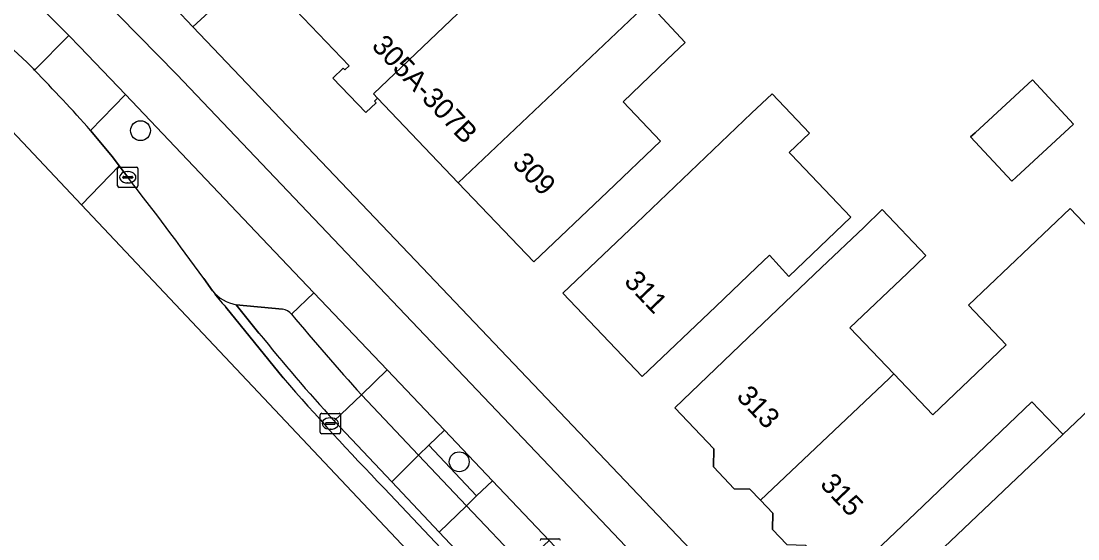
# Model space of a CAD drawing. Extents: x 162523 to 163266, y 381230 to 382050.
# Drawn here: x 162884.1 to 162936.1, y 381486.7 to 381512.1 of the extents above; entities that cross this region are included whole.
import ezdxf

# ---------------------------------------------------------------- set-up
doc = ezdxf.new("R2010")
doc.units = 0
for name, color, linetype in [('IMGEO_Berm_groen', 7, 'Continuous'), ('IMGEO_Berm_open', 7, 'Continuous'), ('IMGEO_Boom', 7, 'Continuous'), ('IMGEO_Erf', 7, 'Continuous'), ('IMGEO_Fietspad_gesloten', 7, 'Continuous'), ('IMGEO_Kolk', 7, 'Continuous'), ('IMGEO_Pand', 7, 'Continuous'), ('IMGEO_Pand_nummerreeks', 7, 'Continuous'), ('IMGEO_Parkeervlak_open', 7, 'Continuous'), ('IMGEO_Rijbaan_lokaal_gesloten', 7, 'Continuous'), ('IMGEO_Rijbaan_lokaal_open', 7, 'Continuous'), ('IMGEO_Voetpad_open', 7, 'Continuous')]:
    doc.layers.add(name, color=color, linetype=linetype)

msp = doc.modelspace()

# ---------------------------------------------------------------- linework, layer by layer
at = {"layer": 'IMGEO_Berm_groen'}
for points in [[(162895.973, 381501.441), (162889.27, 381508.508), (162887.563, 381506.746), (162888.633, 381505.447), (162888.972, 381504.997), (162889.389, 381504.443)], [(162897.444, 381497.706), (162898.543, 381498.758), (162895.973, 381501.441)], [(162893.123, 381499.458), (162893.553, 381498.859)], [(162894.726, 381498.173), (162896.997, 381497.958)]]:
    msp.add_lwpolyline(points, dxfattribs=at)
msp.add_lwpolyline([(162904.958, 381492.006), (162904.184, 381491.264), (162906.542, 381488.775), (162907.318, 381489.521)], close=True, dxfattribs=at)
for centre, radius, start, end in [((162751.131, 381396.99), 175.104, 35.81589, 37.85399), ((162895.072, 381500.111), 1.968, 219.4851, 259.8746), ((162896.897, 381497.258), 0.707, 39.2967, 81.8783)]:
    msp.add_arc(centre, radius, start, end, dxfattribs=at)
at = {"layer": 'IMGEO_Berm_open'}
msp.add_lwpolyline([(162904.184, 381491.264), (162903.687, 381490.773), (162906.04, 381488.29), (162906.542, 381488.775)], close=True, dxfattribs=at)
at = {"layer": 'IMGEO_Boom'}
for centre in [(162890.014, 381506.734), (162905.684, 381490.454)]:
    msp.add_circle(centre, 0.489, dxfattribs=at)
at = {"layer": 'IMGEO_Erf'}
for points in [[(162895.705, 381514.707), (162892.594, 381511.832), (162903.859, 381500), (162947.952, 381453.669)], [(162915.003, 381512.983), (162916.796, 381511.073), (162915.915, 381510.232), (162913.74, 381508.157), (162915.584, 381506.224), (162912.972, 381503.732), (162909.354, 381500.28), (162905.639, 381504.174), (162901.67, 381508.333), (162901.52, 381508.19), (162901.603, 381508.103), (162901.097, 381507.619), (162899.47, 381509.321), (162899.976, 381509.805), (162900.058, 381509.718), (162900.275, 381509.926), (162895.749, 381514.66)], [(162921.802, 381486.381), (162921.086, 381487.132), (162921.104, 381487.935), (162920.503, 381488.564), (162919.981, 381489.111), (162919.209, 381489.129), (162918.187, 381490.2), (162918.208, 381491.09), (162916.28, 381493.109), (162919.897, 381496.562), (162923.5, 381500), (162925.574, 381501.979), (162926.488, 381502.852), (162928.636, 381500.6), (162927.722, 381499.728), (162924.9, 381497.035), (162927.06, 381494.771), (162928.973, 381492.767), (162931.838, 381495.502), (162932.581, 381496.211), (162930.729, 381498.15), (162935.735, 381502.902), (162938.652, 381499.847)], [(162925.959, 381482.861), (162935.374, 381491.799), (162935.349, 381491.825), (162933.844, 381493.401), (162928.117, 381487.935), (162924.5, 381484.482)]]:
    msp.add_lwpolyline(points, dxfattribs=at)
for points in [[(162933.871, 381509.239), (162935.892, 381507.051), (162933.071, 381504.445), (162932.855, 381504.246), (162930.834, 381506.434), (162931.05, 381506.633)], [(162923.972, 381503.5), (162924.946, 381502.479), (162921.897, 381499.569), (162920.938, 381500.605), (162920.304, 381500), (162918.305, 381498.093), (162914.687, 381494.641), (162910.779, 381498.736), (162912.104, 381500), (162914.397, 381502.188), (162920.065, 381507.596), (162921.066, 381508.551), (162922.916, 381506.613), (162921.914, 381505.657), (162922.01, 381505.557)]]:
    msp.add_lwpolyline(points, close=True, dxfattribs=at)
at = {"layer": 'IMGEO_Fietspad_gesloten'}
for points in [[(162884.173, 381513.735), (162886.411, 381511.49), (162886.484, 381511.417), (162887.036, 381510.863), (162889.27, 381508.508), (162895.973, 381501.441), (162898.543, 381498.758), (162902.145, 381494.967), (162904.958, 381492.006), (162907.318, 381489.521), (162910.115, 381486.578), (162917.623, 381478.675), (162920.321, 381475.835), (162923.037, 381472.961), (162924.045, 381471.906), (162924.447, 381471.486), (162928.036, 381467.73), (162928.672, 381467.066), (162936.08, 381459.315), (162938.891, 381456.375)], [(162961.518, 381436.339), (162959.423, 381438.485), (162924.904, 381474.653), (162912.667, 381487.562), (162891.8, 381509.488), (162888.028, 381513.353)]]:
    msp.add_lwpolyline(points, dxfattribs=at)
at = {"layer": 'IMGEO_Kolk'}
for p, q in [((162888.963, 381504.943), (162889.815, 381504.943)), ((162888.888, 381504.017), (162888.888, 381504.869)), ((162889.147, 381504.437), (162889.147, 381504.449)), ((162889.19, 381504.486), (162889.588, 381504.486)), ((162889.376, 381504.723), (162889.401, 381504.723)), ((162889.631, 381504.449), (162889.631, 381504.437)), ((162889.889, 381504.869), (162889.889, 381504.017)), ((162889.815, 381503.943), (162888.963, 381503.943)), ((162889.585, 381504.4), (162889.187, 381504.4)), ((162889.399, 381504.163), (162889.374, 381504.163)), ((162898.849, 381491.909), (162898.849, 381492.761)), ((162898.924, 381492.835), (162899.776, 381492.835)), ((162899.337, 381492.615), (162899.362, 381492.615)), ((162899.85, 381492.761), (162899.85, 381491.909)), ((162899.108, 381492.329), (162899.108, 381492.341)), ((162899.546, 381492.292), (162899.148, 381492.292)), ((162899.151, 381492.378), (162899.549, 381492.378)), ((162899.36, 381492.055), (162899.335, 381492.055)), ((162899.592, 381492.341), (162899.592, 381492.329)), ((162899.776, 381491.835), (162898.924, 381491.835)), ((162909.733, 381486.663), (162910.585, 381486.663))]:
    msp.add_line(p, q, dxfattribs=at)
for points in [[(162888.963, 381504.943), (162889.815, 381504.943)], [(162888.888, 381504.017), (162888.888, 381504.869)], [(162889.889, 381504.869), (162889.889, 381504.017)], [(162889.815, 381503.943), (162888.963, 381503.943)], [(162898.849, 381491.909), (162898.849, 381492.761)], [(162898.924, 381492.835), (162899.776, 381492.835)], [(162899.85, 381492.761), (162899.85, 381491.909)], [(162899.776, 381491.835), (162898.924, 381491.835)], [(162909.733, 381486.663), (162910.585, 381486.663)]]:
    msp.add_lwpolyline(points, dxfattribs=at)
for centre, radius, start, end in [((162888.965, 381504.867), 0.0765, 91.552, 178.448), ((162888.965, 381504.867), 0.0765, 91.552, 178.448), ((162889.813, 381504.867), 0.0765, 1.552, 88.448), ((162889.813, 381504.867), 0.0765, 1.552, 88.448), ((162889.187, 381504.446), 0.0403, 85.8775, 175.7526), ((162889.184, 381504.436), 0.0366, 178.938, 274.7102), ((162889.588, 381504.443), 0.043, 264.8664, 352.4533), ((162889.592, 381504.448), 0.0386, 1.7309, 96.639), ((162888.965, 381504.019), 0.0765, 181.552, 268.448), ((162888.965, 381504.019), 0.0765, 181.552, 268.448), ((162889.813, 381504.019), 0.0765, 271.552, 358.448), ((162889.813, 381504.019), 0.0765, 271.552, 358.448), ((162898.926, 381492.759), 0.0765, 91.552, 178.448), ((162898.926, 381492.759), 0.0765, 91.552, 178.448), ((162899.774, 381492.759), 0.0765, 1.552, 88.448), ((162899.774, 381492.759), 0.0765, 1.552, 88.448), ((162899.148, 381492.338), 0.0403, 85.8775, 175.7526), ((162899.145, 381492.328), 0.0366, 178.938, 274.7102), ((162899.549, 381492.335), 0.043, 264.8664, 352.4533), ((162899.553, 381492.34), 0.0386, 1.7309, 96.639), ((162898.926, 381491.911), 0.0765, 181.552, 268.448), ((162898.926, 381491.911), 0.0765, 181.552, 268.448), ((162899.774, 381491.911), 0.0765, 271.552, 358.448), ((162899.774, 381491.911), 0.0765, 271.552, 358.448), ((162909.735, 381486.587), 0.0765, 91.552, 178.448), ((162909.735, 381486.587), 0.0765, 91.552, 178.448), ((162910.583, 381486.587), 0.0765, 1.552, 88.448), ((162910.583, 381486.587), 0.0765, 1.552, 88.448)]:
    msp.add_arc(centre, radius, start, end, dxfattribs=at)
for centre, major_axis, ratio, start_param, end_param in [((162889.375, 381504.443), (-0.387, 0.002), 0.722429, 4.712389, 7.853982), ((162889.4, 381504.443), (-0.39, 0.002), 0.717154, 1.570796, 4.712389), ((162899.336, 381492.335), (-0.387, 0.002), 0.722429, 4.712389, 7.853982), ((162899.361, 381492.335), (-0.39, 0.002), 0.717154, 1.570796, 4.712389)]:
    msp.add_ellipse(centre, major_axis=major_axis, ratio=ratio, start_param=start_param, end_param=end_param, dxfattribs=at)
at = {"layer": 'IMGEO_Pand'}
for points in [[(162919.474, 381526.944), (162909.923, 381537.019), (162909.814, 381536.915), (162905.379, 381532.694), (162902.834, 381530.267), (162907.255, 381525.636), (162895.749, 381514.66), (162900.275, 381509.926), (162900.058, 381509.718), (162899.976, 381509.805), (162899.47, 381509.321), (162901.097, 381507.619), (162901.603, 381508.103), (162901.52, 381508.19), (162901.67, 381508.333), (162901.466, 381508.547), (162907.675, 381514.471), (162907.001, 381515.177), (162912.284, 381520.218)], [(162928.435, 381525.823), (162923.628, 381530.824), (162919.474, 381526.944), (162912.284, 381520.218), (162907.001, 381515.177), (162907.675, 381514.471), (162901.466, 381508.547), (162901.67, 381508.333), (162905.639, 381504.174), (162914.973, 381513.014), (162915.003, 381512.983), (162915.907, 381513.903)], [(162913.74, 381508.157), (162915.915, 381510.232), (162916.796, 381511.073), (162915.003, 381512.983), (162914.973, 381513.014), (162905.639, 381504.174), (162909.354, 381500.28), (162912.972, 381503.732), (162915.584, 381506.224)], [(162933.844, 381493.401), (162935.349, 381491.825), (162935.374, 381491.799), (162948.134, 381503.914), (162951.885, 381507.475), (162946.401, 381513.222), (162941.842, 381508.894), (162944.855, 381505.737), (162938.652, 381499.847), (162935.735, 381502.902), (162930.729, 381498.15), (162932.581, 381496.211), (162931.838, 381495.502), (162928.973, 381492.767), (162927.06, 381494.771), (162926.828, 381494.547), (162920.503, 381488.564), (162921.104, 381487.935), (162921.086, 381487.132), (162921.802, 381486.381), (162922.707, 381486.36), (162924.5, 381484.482), (162928.117, 381487.935)], [(162935.892, 381507.051), (162933.871, 381509.239), (162931.05, 381506.633), (162930.834, 381506.434), (162932.855, 381504.246), (162933.071, 381504.445)], [(162923.972, 381503.5), (162922.01, 381505.557), (162921.914, 381505.657), (162922.916, 381506.613), (162921.066, 381508.551), (162920.065, 381507.596), (162914.397, 381502.188), (162912.104, 381500), (162910.779, 381498.736), (162914.687, 381494.641), (162918.305, 381498.093), (162920.304, 381500), (162920.938, 381500.605), (162921.897, 381499.569), (162924.946, 381502.479)], [(162954.918, 381500.53), (162956.799, 381502.326), (162951.885, 381507.475), (162948.134, 381503.914), (162935.374, 381491.799), (162925.959, 381482.861), (162926.338, 381482.463), (162929.997, 381478.63), (162930.329, 381478.283), (162933.973, 381481.762), (162939.885, 381487.405), (162940.499, 381486.762), (162948.656, 381494.551), (162950.818, 381496.616)], [(162924.9, 381497.035), (162927.722, 381499.728), (162928.636, 381500.6), (162926.488, 381502.852), (162925.574, 381501.979), (162923.5, 381500), (162919.897, 381496.562), (162916.28, 381493.109), (162918.208, 381491.09), (162918.187, 381490.2), (162919.209, 381489.129), (162919.981, 381489.111), (162920.503, 381488.564), (162926.828, 381494.547), (162927.06, 381494.771)]]:
    msp.add_lwpolyline(points, close=True, dxfattribs=at)
at = {"layer": 'IMGEO_Parkeervlak_open'}
for points in [[(162896.997, 381497.958), (162894.726, 381498.173), (162895.836, 381496.785)], [(162899.535, 381492.474), (162900.875, 381493.741)]]:
    msp.add_lwpolyline(points, dxfattribs=at)
msp.add_lwpolyline([(162903.687, 381490.773), (162902.368, 381489.469), (162904.702, 381486.995), (162906.04, 381488.29)], close=True, dxfattribs=at)
for centre, radius, start, end in [((162896.897, 381497.258), 0.707, 39.2967, 81.8783), ((163000.293, 381583.237), 133.766, 219.74733, 221.99336), ((162967.973, 381554.939), 92.659, 218.8743, 222.38736)]:
    msp.add_arc(centre, radius, start, end, dxfattribs=at)
at = {"layer": 'IMGEO_Rijbaan_lokaal_gesloten'}
for points in [[(162850.481, 381537.747), (162852.361, 381535.919), (162852.388, 381535.891), (162852.552, 381535.73), (162860.285, 381529.415), (162869.434, 381520.637), (162881.316, 381509.236), (162887.11, 381503.092)], [(162884.801, 381509.715), (162884.75, 381509.767), (162884.448, 381510.078), (162882.392, 381511.969), (162876.833, 381517.342), (162876.506, 381517.69)], [(162887.11, 381503.092), (162888.972, 381504.997), (162888.633, 381505.447), (162887.563, 381506.746)], [(162889.389, 381504.443), (162888.972, 381504.997), (162887.11, 381503.092)], [(162887.11, 381503.092), (162963.914, 381421.653), (162967.157, 381418.214), (163074.793, 381306.702), (163143.693, 381232.736), (163143.732, 381232.914), (163146.87, 381246.552), (163146.483, 381246.256), (163145.74, 381245.612)], [(162893.553, 381498.859), (162893.123, 381499.458)], [(162897.034, 381494.573), (162894.209, 381498.061)], [(163021.301, 381363.034), (163013.088, 381371.672), (162986.682, 381399.65), (162986.368, 381399.99), (162985.524, 381400.871), (162976.597, 381410.3), (162973.7, 381413.358), (162972.718, 381414.396), (162971.1, 381416.115), (162960.882, 381426.909), (162960.098, 381427.764), (162957.731, 381430.254), (162919.892, 381470.214), (162901.988, 381489.161)]]:
    msp.add_lwpolyline(points, dxfattribs=at)
for centre, radius, start, end in [((162803.403, 381431.223), 113.078, 41.90402, 43.95881), ((162751.131, 381396.99), 175.104, 35.81589, 37.85399), ((162900.233, 381503.681), 8.238, 215.8276, 223.0166), ((163001.949, 381585.636), 138.923, 220.95697, 223.98333)]:
    msp.add_arc(centre, radius, start, end, dxfattribs=at)
at = {"layer": 'IMGEO_Rijbaan_lokaal_open'}
for points in [[(162887.036, 381510.863), (162886.484, 381511.417), (162884.801, 381509.715)], [(162887.563, 381506.746), (162889.27, 381508.508), (162887.036, 381510.863)], [(162894.209, 381498.061), (162897.034, 381494.573)], [(162895.836, 381496.785), (162894.726, 381498.173)], [(162920.135, 381470.628), (162917.662, 381473.25), (162914.949, 381476.128), (162907.46, 381484.07), (162904.702, 381486.995), (162902.368, 381489.469), (162899.535, 381492.474)], [(162901.988, 381489.161), (162919.892, 381470.214), (162957.731, 381430.254)]]:
    msp.add_lwpolyline(points, dxfattribs=at)
for points in [[(162902.145, 381494.967), (162900.875, 381493.741), (162903.687, 381490.773), (162904.184, 381491.264), (162904.958, 381492.006)], [(162900.875, 381493.741), (162899.535, 381492.474), (162902.368, 381489.469), (162903.687, 381490.773)], [(162907.318, 381489.521), (162906.542, 381488.775), (162906.04, 381488.29), (162908.814, 381485.363), (162909.305, 381485.832), (162910.115, 381486.578)], [(162906.04, 381488.29), (162904.702, 381486.995), (162907.46, 381484.07), (162908.814, 381485.363)]]:
    msp.add_lwpolyline(points, close=True, dxfattribs=at)
for centre, radius, start, end in [((162803.403, 381431.223), 113.078, 41.90402, 43.95881), ((162895.072, 381500.111), 1.968, 219.4851, 259.8746), ((162900.233, 381503.681), 8.238, 215.8276, 223.0166), ((162967.973, 381554.939), 92.659, 218.8743, 222.38736), ((163001.949, 381585.636), 138.923, 220.95697, 223.98333)]:
    msp.add_arc(centre, radius, start, end, dxfattribs=at)
at = {"layer": 'IMGEO_Voetpad_open'}
for points in [[(162903.859, 381500), (162892.594, 381511.832), (162888.242, 381516.445), (162890.13, 381518.183), (162885.5, 381523.02), (162878.388, 381531.449), (162877.207, 381530.003)], [(162888.028, 381513.353), (162891.8, 381509.488), (162912.667, 381487.562), (162924.904, 381474.653), (162959.423, 381438.485), (162961.518, 381436.339)], [(162976.233, 381421.393), (162979.022, 381417.976), (162980.035, 381416.858), (162981.376, 381418.11), (162981.097, 381418.403), (162983.379, 381420.58), (162976.626, 381427.791), (162972.114, 381431.768), (162970.134, 381435.285), (162965.5, 381435.272), (162950.743, 381450.74), (162949.274, 381452.279), (162949.085, 381452.478), (162948.785, 381452.793), (162947.952, 381453.669), (162903.859, 381500)], [(162898.543, 381498.758), (162897.444, 381497.706)], [(162900.875, 381493.741), (162902.145, 381494.967), (162898.543, 381498.758)]]:
    msp.add_lwpolyline(points, dxfattribs=at)
for points in [[(162891.392, 381519.353), (162890.13, 381518.183), (162888.242, 381516.445), (162892.594, 381511.832), (162895.705, 381514.707)], [(162884.173, 381513.735), (162884.116, 381513.801), (162882.392, 381511.969), (162884.448, 381510.078), (162884.75, 381509.767), (162884.801, 381509.715), (162886.484, 381511.417), (162886.411, 381511.49)]]:
    msp.add_lwpolyline(points, close=True, dxfattribs=at)
msp.add_arc((163000.293, 381583.237), 133.766, 219.74733, 221.99336, dxfattribs=at)

# ---------------------------------------------------------------- texts
at = {"layer": 'IMGEO_Pand_nummerreeks'}
for s, rotation, p in [('305A-307B', 313.6592, (162901.334, 381510.858)), ('309', 313.6534, (162908.254, 381505.085)), ('311', 313.6592, (162913.747, 381499.277)), ('313', 313.6133, (162919.272, 381493.622)), ('315', 313.6133, (162923.382, 381489.308))]:
    msp.add_text(s, height=1, rotation=rotation, dxfattribs=at).set_placement(p)

doc.saveas('drawing.dxf')
